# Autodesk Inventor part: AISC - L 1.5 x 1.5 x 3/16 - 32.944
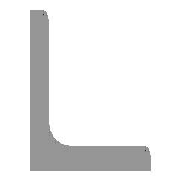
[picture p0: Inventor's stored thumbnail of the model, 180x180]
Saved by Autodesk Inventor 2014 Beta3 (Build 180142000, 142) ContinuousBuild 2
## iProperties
IsCustomPart: 1
Created: 2010-11
Part Number: AISC - L 1.5 x 1.5 x 3/16 - 32.944
Material: Steel, Mild
Description: Angle Steel
Document SubType Name: Modeling
Standard: ANSI
Designer: Beta-8540w
Standards Organization: ANSI
Language: en-US
Size Designation: L 1.5 x 1.5 x 3/16
Categories: <MemberInstance><Categories><Category DisplayName="Structural Shapes" InternalName="089c4875-fa83-4c05-b084-43b9cc11f5ed" Mnemonic="GRDR"><CategoryParameter Dis
Stock Number: L 1.5 x 1.5 x 3/16
Density: 7.86 g/cm^3
Appearance: Steel
_CCFamilyMember: 5
_CCFamilyDisplayName: ANSI L (Equal angles) - Angle Steel
_FrameMemberDoc: Frame Member File
_Version: 15.0.0
_GetPNFromCC: 1
G_L: 32.944 in
G_W: 1.500 in
G_H: 1.500 in
Author: Beta-8540w
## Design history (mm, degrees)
node "Start plane"
node "End plane"
sketch "Sketch"
  geometry: L1 (38.1, 0)-(0, 0); L2 (0, 0)-(0, 38.1); L3 (0, 38.1)-(2.476, 38.1); L4 (4.762, 35.814)-(4.762, 9.589); L5 (9.588, 4.763)-(35.814, 4.763); L6 (38.1, 2.477)-(38.1, 0); L7 (0, -11.041)-(0, 31.538); L8 (-11.041, 0)-(31.538, 0); L9 (0, 48.496)-(0, -20.964) reference; L10 (-20.964, 0)-(48.496, 0) reference; A1 r 4.826 centre (9.588, 9.589) between (4.762, 9.589) and (9.588, 4.763); A2 r 2.286 centre (2.476, 35.814) between (4.762, 35.814) and (2.476, 38.1); A3 r 2.286 centre (35.814, 2.477) between (38.1, 2.477) and (35.814, 4.763); 3 further points
  constraints: 16 end point, 6 point on circle, 6 point on line, 6 tangent, 4 parallel, 3 centre point, 2 collinear, 1 equal radius, 1 horizontal, 1 perpendicular
  dimensions: "d0" = 38.1 distance between parallel lines of L6 L2 (= G_H); "d1" = 38.1 distance between parallel lines of L3 L1 (= G_H); "d2" = 4.7625 distance between parallel lines of L2 L4 (= G_T); "d3" = 4.7625 distance between parallel lines of L1 L5 (= G_T); "d10" = 0 distance between parallel lines of L7 L2 (computed from ex); "d11" = 0 distance between parallel lines of L8 L1 (computed from d10); "d14" = 4.826 radius of A1 (= G_IR); "d15" = 2.286 radius of A2 (= G_ER)
extrude "Body" new body sketch "Sketch" stored distance "d4" = 836.76542 (= G_L); taper "d5" = 0 deg
node "Driven Length"
  sketch "Sketch3"
    geometry: L1 (0, 0)-(10, 0) reference
    constraints: 2 end point, 1 horizontal
  workplane "Work Plane3"
  sketch "Sketch4"
    geometry: L1 (-2, 0)-(12, 0) reference; L2 (-2, 836.765)-(12, 836.765) reference
    dimensions: "d17" = 836.76542 distance between parallel lines of L1 L2 (derived)
body "Solid1"
other parameters: "G_H" = 38.1 [user parameter; used in 2 equation terms], "G_T" = 4.7625 [user parameter; used in 2 equation terms], "G_ER" = 2.286 [user parameter; used in 1 equation term], "G_IR" = 4.826 [user parameter; used in 1 equation term], "G_L" = 836.76542 (= d17) [user parameter; used in 1 equation term], "ex" = 0 [user parameter; used in 1 equation term], "G_OFFSET_START" = 0 [user parameter; used in 1 equation term], "G_OFFSET_END" = 0 [user parameter; used in 1 equation term], "d12" = 0 (computed from G_OFFSET_START), "d13" = 836.76542 (= G_OFFSET_END + B_L), "B_L" = 836.76542 [user parameter; used in 1 equation term], "d16" = 90 deg, "MAS" = 0.26787 [user parameter]
